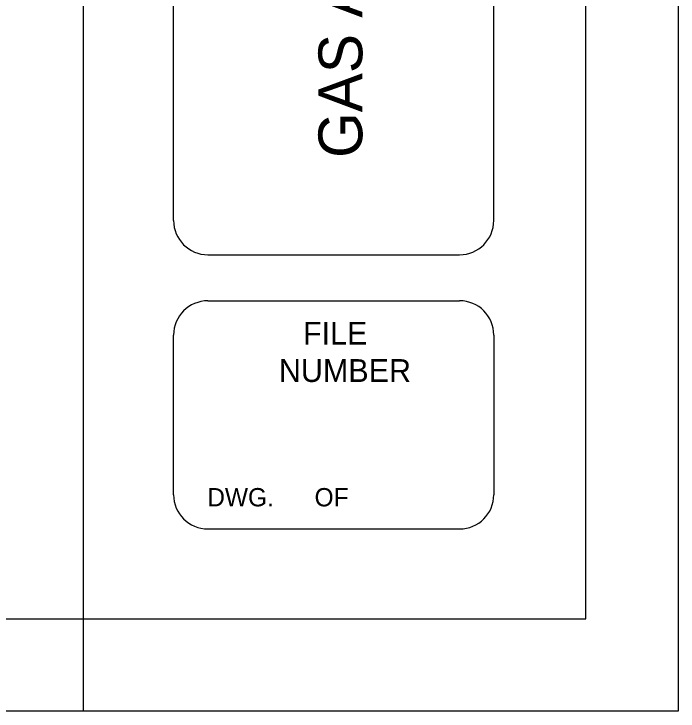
# Model space of a CAD drawing. Extents: x 22422.9 to 22498.9, y 22369.6 to 22415.
# Drawn here: x 22494.08 to 22498.93, y 22369.62 to 22374.71 of the extents above; entities that cross this region are included whole.
import ezdxf

# ---------------------------------------------------------------- set-up
doc = ezdxf.new("R2010")
doc.units = 0
for name, color, linetype in [('Level 1', 7, 'Continuous'), ('Level 10', 7, 'Continuous'), ('Level 2', 7, 'Continuous'), ('Level 3', 7, 'Continuous'), ('Level 9', 7, 'Continuous')]:
    doc.layers.add(name, color=color, linetype=linetype)

msp = doc.modelspace()

# ---------------------------------------------------------------- linework, layer by layer
at = {"layer": 'Level 1'}
for p, q in [((22495.4969, 22372.9493), (22497.3329, 22372.9493)), ((22495.4969, 22372.6133), (22497.3329, 22372.6133)), ((22495.4969, 22370.9493), (22497.3329, 22370.9493)), ((22494.1749, 22370.2933), (22494.8469, 22370.2933))]:
    msp.add_line(p, q, dxfattribs=at)
msp.add_lwpolyline([(22440.2597, 22414.9653), (22498.9269, 22414.9653), (22498.9269, 22369.6213), (22440.2597, 22369.6213)], close=True, dxfattribs=at)
for points in [[(22495.2469, 22373.1993), (22495.2469, 22379.3713)], [(22497.5829, 22373.1993), (22497.5829, 22379.3713)], [(22495.2469, 22371.1993), (22495.2469, 22372.3633)], [(22497.5829, 22372.3633), (22497.5829, 22371.1993)]]:
    msp.add_lwpolyline(points, dxfattribs=at)
for centre, start, end in [((22495.4969, 22373.1993), 180, 270), ((22497.3329, 22373.1993), 270, 0), ((22495.4969, 22372.3633), 90, 180), ((22497.3329, 22372.3633), 0, 90), ((22495.4969, 22371.1993), 180, 270), ((22497.3329, 22371.1993), 270, 0)]:
    msp.add_arc(centre, 0.25, start, end, dxfattribs=at)
at = {"layer": 'Level 10'}
msp.add_line((22494.5909, 22369.6213), (22494.5909, 22370.2933), dxfattribs=at)
at = {"layer": 'Level 9'}
for p, q in [((22498.2549, 22370.2933), (22498.2549, 22414.2933)), ((22442.2597, 22370.2933), (22494.5909, 22370.2933)), ((22494.5909, 22370.2933), (22498.2549, 22370.2933))]:
    msp.add_line(p, q, dxfattribs=at)
msp.add_lwpolyline([(22494.5909, 22370.2933), (22494.5909, 22414.2933)], dxfattribs=at)

# ---------------------------------------------------------------- texts
at = {"layer": 'Level 2'}
for s, height, p in [('FILE', 0.16637, (22496.1909, 22372.2933)), ('NUMBER', 0.16637, (22496.0149, 22372.0213)), ('DWG.      OF  ', 0.133344, (22495.4927, 22371.1142))]:
    msp.add_text(s, height=height, dxfattribs=at).set_placement(p)
at = {"layer": 'Level 3'}
msp.add_text('GAS AND PETROLEUM', height=0.32, rotation=90, dxfattribs=at).set_placement((22496.6237, 22373.6553))

doc.saveas('drawing.dxf')
